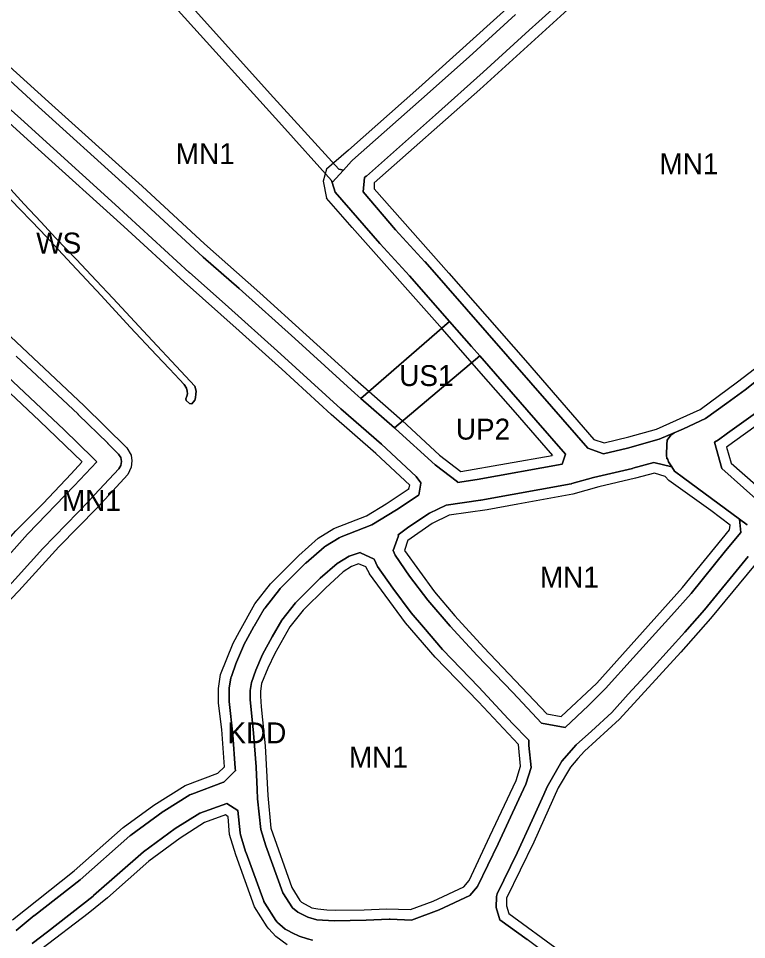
# Model space of a CAD drawing. Extents: x -284239 to -281592, y 34477 to 37267.
# Drawn here: x -283861.3 to -283512.6, y 35288.9 to 35729.6 of the extents above; entities that cross this region are included whole.
import ezdxf

# ---------------------------------------------------------------- set-up
doc = ezdxf.new("R2010")
doc.units = 0
for name, color, linetype in [('linie_rozgraniczajace', 7, 'Continuous'), ('linie_zabudowy_nieprzekraczalne', 7, 'Continuous'), ('oznaczenia_przeznaczen', 7, 'Continuous')]:
    doc.layers.add(name, color=color, linetype=linetype)

msp = doc.modelspace()

# ---------------------------------------------------------------- linework, layer by layer
at = {"layer": 'linie_rozgraniczajace'}
for points in [[(-283808.955, 35769.886), (-283783.5, 35741.024), (-283780.8, 35738.036), (-283740.666, 35693.613), (-283707.899, 35657.552), (-283705.683, 35657.06), (-283711.093, 35651.189), (-283711.377, 35652.06), (-283735.174, 35678.603), (-283784.744, 35733.443), (-283790.273, 35739.559), (-283815.534, 35767.383), (-283817.232, 35767.227), (-283817.23, 35767.269), (-283824.445, 35774.068), (-283832.86, 35774.502)], [(-283582.255, 35755.055), (-283612.122, 35728.101), (-283616.645, 35723.99), (-283638.785, 35703.867), (-283638.811, 35703.846), (-283661.609, 35683.477), (-283694.657, 35654.221), (-283694.732, 35654.154), (-283695.579, 35653.436), (-283696.185, 35646.675), (-283680.653, 35628.497), (-283666.588, 35613.191), (-283666.552, 35613.135), (-283666.511, 35613.105), (-283636.802, 35579.241), (-283605.981, 35543.988), (-283588.549, 35523.959), (-283581.071, 35521.348), (-283569.642, 35524.059), (-283554.422, 35528.287), (-283547.243, 35531.389), (-283548.812, 35530.257), (-283550.583, 35527.86), (-283550.792, 35525.775), (-283550.896, 35520.877), (-283550.711, 35518.939), (-283550.518, 35518.992), (-283550.062, 35517.542), (-283548.466, 35515.033), (-283556.983, 35517.221), (-283567.06, 35514.398), (-283567.127, 35514.388), (-283567.249, 35514.349), (-283585.931, 35509.938), (-283596.199, 35507.032), (-283596.388, 35507.006), (-283596.669, 35506.923), (-283639.858, 35499.094), (-283639.977, 35499.083), (-283640.053, 35499.063), (-283656.447, 35496.757), (-283664.447, 35492.93), (-283674.315, 35486.435), (-283679.45, 35482.48), (-283679.321, 35482.071), (-283681.841, 35475.084), (-283680.864, 35472.739), (-283673.957, 35462.829), (-283665.249, 35451.269), (-283654.589, 35438.807), (-283641.677, 35424.844), (-283624.486, 35407.053)], [(-283496.755, 35565.013), (-283513.325, 35551.986), (-283522.028, 35545.577), (-283532.345, 35538.177), (-283542.871, 35533.279), (-283547.243, 35531.389), (-283554.422, 35528.287), (-283569.642, 35524.059), (-283581.071, 35521.348), (-283588.549, 35523.959), (-283605.981, 35543.988), (-283636.802, 35579.241), (-283666.511, 35613.105), (-283666.552, 35613.135), (-283666.588, 35613.191), (-283680.653, 35628.497), (-283696.185, 35646.675), (-283695.579, 35653.436), (-283694.732, 35654.154), (-283694.657, 35654.221), (-283661.609, 35683.477), (-283638.811, 35703.846), (-283638.785, 35703.867), (-283616.645, 35723.99), (-283612.122, 35728.101), (-283582.255, 35755.055)], [(-283623.204, 35731.542), (-283645.495, 35711.281), (-283668.253, 35690.949), (-283701.237, 35661.749), (-283701.793, 35661.281), (-283705.683, 35657.06), (-283707.899, 35657.552), (-283740.666, 35693.613), (-283780.8, 35738.036)], [(-283784.744, 35733.443), (-283735.174, 35678.603), (-283711.377, 35652.06), (-283711.093, 35651.189), (-283709.551, 35646.459), (-283688.197, 35621.932), (-283688.134, 35621.887), (-283688.077, 35621.797), (-283673.99, 35606.467), (-283654.775, 35584.565), (-283697.303, 35547.75), (-283700.247, 35550.318), (-283728.872, 35576.454), (-283728.901, 35576.477), (-283755.566, 35600.375), (-283755.59, 35600.39), (-283755.606, 35600.413), (-283772.734, 35615.466), (-283808.228, 35648.053), (-283853.453, 35688.985), (-283875.706, 35709.29)], [(-283875.706, 35709.29), (-283853.453, 35688.985), (-283808.228, 35648.053), (-283772.734, 35615.466), (-283755.606, 35600.413), (-283755.59, 35600.39), (-283755.566, 35600.375), (-283728.901, 35576.477), (-283728.872, 35576.454), (-283700.247, 35550.318), (-283697.303, 35547.75), (-283681.245, 35533.742), (-283680.762, 35533.321), (-283680.718, 35533.26), (-283680.635, 35533.206), (-283661.767, 35516.043), (-283651.032, 35507.834), (-283650.975, 35507.625), (-283641.544, 35508.951), (-283600.922, 35516.315), (-283600.896, 35516.422), (-283599.331, 35521.115), (-283613.517, 35537.415), (-283640.395, 35568.158), (-283644.325, 35572.653), (-283654.775, 35584.565), (-283673.99, 35606.467), (-283688.077, 35621.797), (-283688.134, 35621.887), (-283688.197, 35621.932), (-283709.551, 35646.459), (-283711.093, 35651.189), (-283705.683, 35657.06), (-283701.793, 35661.281), (-283701.237, 35661.749), (-283668.253, 35690.949), (-283645.495, 35711.281), (-283623.204, 35731.542)], [(-283714.87, 35476.613), (-283714.661, 35476.741), (-283714.236, 35477.078), (-283707.712, 35481.123), (-283706.991, 35481.493), (-283706.797, 35481.532), (-283706.659, 35481.617), (-283692.076, 35487.249), (-283680.271, 35494.47), (-283680.14, 35494.546), (-283679.969, 35494.686), (-283669.661, 35501.471), (-283669.616, 35501.494), (-283668.586, 35507.329), (-283668.529, 35507.443), (-283670.842, 35510.369), (-283687.4, 35525.841), (-283706.863, 35542.82), (-283706.892, 35542.859), (-283706.948, 35542.895), (-283735.598, 35569.054), (-283762.222, 35592.912), (-283779.377, 35607.992), (-283779.404, 35608.03), (-283779.457, 35608.064), (-283814.967, 35640.666), (-283860.177, 35681.585), (-283882.985, 35701.865)], [(-283882.985, 35701.865), (-283860.177, 35681.585), (-283814.967, 35640.666), (-283779.457, 35608.064), (-283779.404, 35608.03), (-283779.377, 35607.992), (-283762.222, 35592.912), (-283735.598, 35569.054), (-283706.948, 35542.895), (-283706.892, 35542.859), (-283706.863, 35542.82), (-283687.4, 35525.841), (-283670.842, 35510.369), (-283668.529, 35507.443), (-283668.586, 35507.329), (-283669.616, 35501.494), (-283669.661, 35501.471), (-283679.969, 35494.686), (-283680.14, 35494.546), (-283680.271, 35494.47), (-283692.076, 35487.249), (-283706.659, 35481.617), (-283706.797, 35481.532), (-283706.991, 35481.493), (-283707.712, 35481.123), (-283714.236, 35477.078), (-283714.661, 35476.741), (-283714.87, 35476.613)], [(-283864.887, 35642.802), (-283850.707, 35628.208), (-283835.698, 35612.105), (-283821.67, 35596.983), (-283807.792, 35581.937), (-283795.197, 35568.474), (-283788.937, 35561.95), (-283784.185, 35556.821), (-283781.922, 35554.407), (-283780.791, 35552.748), (-283780.414, 35551.315), (-283780.339, 35550.033), (-283780.565, 35548.826), (-283781.093, 35547.62), (-283780.942, 35546.79), (-283779.358, 35545.432), (-283778.302, 35545.206), (-283776.718, 35546.941), (-283776.492, 35548.148), (-283776.341, 35550.033), (-283776.19, 35551.164), (-283776.417, 35552.597), (-283776.794, 35553.729), (-283783.431, 35560.856), (-283799.269, 35577.788), (-283816.013, 35595.776), (-283823.932, 35604.073), (-283833.662, 35614.368), (-283843.391, 35624.512), (-283850.556, 35632.281), (-283858.476, 35640.766), (-283871.373, 35654.832)], [(-283871.373, 35654.832), (-283858.476, 35640.766), (-283850.556, 35632.281), (-283843.391, 35624.512), (-283833.662, 35614.368), (-283823.932, 35604.073), (-283816.013, 35595.776), (-283799.269, 35577.788), (-283783.431, 35560.856), (-283776.794, 35553.729), (-283776.417, 35552.597), (-283776.19, 35551.164), (-283776.341, 35550.033), (-283776.492, 35548.148), (-283776.718, 35546.941), (-283778.302, 35545.206), (-283779.358, 35545.432), (-283780.942, 35546.79), (-283781.093, 35547.62), (-283780.565, 35548.826), (-283780.339, 35550.033), (-283780.414, 35551.315), (-283780.791, 35552.748), (-283781.922, 35554.407), (-283784.185, 35556.821), (-283788.937, 35561.95), (-283795.197, 35568.474), (-283807.792, 35581.937), (-283821.67, 35596.983), (-283835.698, 35612.105), (-283850.707, 35628.208), (-283864.887, 35642.802)], [(-283862.396, 35568.049), (-283832.706, 35540.21), (-283832.681, 35540.175), (-283832.641, 35540.148), (-283818.486, 35526.39), (-283818.447, 35526.333), (-283818.39, 35526.294), (-283813.297, 35521.069), (-283812.258, 35519.492), (-283811.877, 35517.579), (-283812.258, 35515.665), (-283813.216, 35514.174), (-283827.239, 35499.093), (-283827.281, 35499.063), (-283827.313, 35499.014), (-283849.606, 35476.062), (-283868.791, 35454.767)], [(-283868.791, 35454.767), (-283849.606, 35476.062), (-283827.313, 35499.014), (-283827.281, 35499.063), (-283827.239, 35499.093), (-283813.216, 35514.174), (-283812.258, 35515.665), (-283811.877, 35517.579), (-283812.258, 35519.492), (-283813.297, 35521.069), (-283818.39, 35526.294), (-283818.447, 35526.333), (-283818.486, 35526.39), (-283832.641, 35540.148), (-283832.681, 35540.175), (-283832.706, 35540.21), (-283862.396, 35568.049)], [(-283512.308, 35487.34), (-283516.02, 35490.071), (-283542.871, 35509.83), (-283547.144, 35512.956), (-283548.466, 35515.033), (-283550.062, 35517.542), (-283550.518, 35518.992), (-283550.711, 35518.939), (-283550.896, 35520.877), (-283550.792, 35525.775), (-283550.583, 35527.86), (-283548.812, 35530.257), (-283547.243, 35531.389), (-283542.871, 35533.279), (-283532.345, 35538.177), (-283522.028, 35545.577), (-283513.325, 35551.986), (-283496.755, 35565.013)], [(-283876.156, 35461.533), (-283856.972, 35482.826), (-283856.901, 35482.875), (-283856.844, 35482.962), (-283834.525, 35505.942), (-283823.78, 35517.497), (-283825.504, 35519.266), (-283839.578, 35532.946), (-283869.253, 35560.771)], [(-283869.253, 35560.771), (-283839.578, 35532.946), (-283825.504, 35519.266), (-283823.78, 35517.497), (-283834.525, 35505.942), (-283856.844, 35482.962), (-283856.901, 35482.875), (-283856.972, 35482.826), (-283876.156, 35461.533)], [(-283507.177, 35541.564), (-283521.715, 35531.195), (-283525.988, 35527.964), (-283527.946, 35526.924), (-283524.385, 35514.239), (-283503.633, 35495.708)], [(-283503.633, 35495.708), (-283524.385, 35514.239), (-283527.946, 35526.924), (-283525.988, 35527.964), (-283521.715, 35531.195), (-283507.177, 35541.564)], [(-283624.486, 35407.053), (-283615.328, 35397.143), (-283610.767, 35392.355), (-283599.518, 35390.409), (-283588.303, 35400.897), (-283580.12, 35408.93), (-283566.908, 35423.643), (-283548.516, 35443.987), (-283539.057, 35454.497), (-283522.617, 35474.841), (-283515.386, 35483.607), (-283516.02, 35490.071), (-283512.308, 35487.34)], [(-283862.327, 35293.261), (-283853.715, 35300.32), (-283853.69, 35300.335), (-283853.628, 35300.389), (-283831.779, 35317.5), (-283807.875, 35338.507), (-283807.792, 35338.559), (-283807.519, 35338.792), (-283791.909, 35350.169), (-283791.743, 35350.262), (-283791.589, 35350.383), (-283779.154, 35358.057), (-283778.442, 35358.421), (-283778.344, 35358.44), (-283778.268, 35358.489), (-283763.121, 35364.111), (-283762.9, 35364.151), (-283757.468, 35369.583), (-283757.377, 35369.666), (-283757.434, 35370.885), (-283758.597, 35386.779), (-283760.348, 35402.804), (-283760.378, 35403.347), (-283760.378, 35408.436), (-283760.31, 35409.258), (-283759.527, 35413.956), (-283759.334, 35414.63), (-283759.3, 35414.827), (-283756.951, 35421.351), (-283756.868, 35421.482), (-283756.834, 35421.646), (-283753.435, 35429.484), (-283753.258, 35429.853), (-283748.561, 35438.596), (-283748.527, 35438.642), (-283748.462, 35438.771), (-283743.569, 35447.057), (-283743.341, 35447.351), (-283743.185, 35447.617), (-283736.269, 35456.359), (-283735.883, 35456.792), (-283723.749, 35468.927), (-283723.579, 35469.041), (-283723.481, 35469.176), (-283714.87, 35476.613)], [(-283714.87, 35476.613), (-283723.481, 35469.176), (-283723.579, 35469.041), (-283723.749, 35468.927), (-283735.883, 35456.792), (-283736.269, 35456.359), (-283743.185, 35447.617), (-283743.341, 35447.351), (-283743.569, 35447.057), (-283748.462, 35438.771), (-283748.527, 35438.642), (-283748.561, 35438.596), (-283753.258, 35429.853), (-283753.435, 35429.484), (-283756.834, 35421.646), (-283756.868, 35421.482), (-283756.951, 35421.351), (-283759.3, 35414.827), (-283759.334, 35414.63), (-283759.527, 35413.956), (-283760.31, 35409.258), (-283760.378, 35408.436), (-283760.378, 35403.347), (-283760.348, 35402.804), (-283758.597, 35386.779), (-283757.434, 35370.885), (-283757.377, 35369.666), (-283757.468, 35369.583), (-283762.9, 35364.151), (-283763.121, 35364.111), (-283778.268, 35358.489), (-283778.344, 35358.44), (-283778.442, 35358.421), (-283779.154, 35358.057), (-283791.589, 35350.383), (-283791.743, 35350.262), (-283791.909, 35350.169), (-283807.519, 35338.792), (-283807.792, 35338.559), (-283807.875, 35338.507), (-283831.779, 35317.5), (-283853.628, 35300.389), (-283853.69, 35300.335), (-283853.715, 35300.32), (-283862.327, 35293.261)], [(-283511.807, 35472.138), (-283532.826, 35446.614), (-283542.135, 35435.955), (-283557.224, 35419.364), (-283569.31, 35406.227), (-283577.117, 35397.519), (-283586.876, 35388.661), (-283594.158, 35381.979), (-283601.125, 35374.211), (-283608.121, 35362.011), (-283609.622, 35358.258), (-283615.253, 35346.021), (-283622.459, 35330.407), (-283631.993, 35310.813), (-283632.294, 35309.462), (-283632.444, 35304.207), (-283630.702, 35298.362), (-283617.703, 35288.854)], [(-283632.444, 35304.207), (-283632.294, 35309.462), (-283631.993, 35310.813), (-283622.459, 35330.407), (-283615.253, 35346.021), (-283609.622, 35358.258), (-283608.121, 35362.011), (-283601.125, 35374.211), (-283594.158, 35381.979), (-283586.876, 35388.661), (-283577.117, 35397.519), (-283569.31, 35406.227), (-283557.224, 35419.364), (-283542.135, 35435.955), (-283532.826, 35446.614), (-283511.807, 35472.138)], [(-283720.495, 35288.596), (-283722.896, 35289.305), (-283726.771, 35290.451), (-283730.258, 35292.156), (-283732.339, 35293.174), (-283733.503, 35293.917), (-283736.076, 35296.108), (-283737.026, 35296.917), (-283737.319, 35297.188), (-283737.974, 35297.997), (-283743.324, 35306.217), (-283743.753, 35307.031), (-283743.832, 35307.237), (-283752.248, 35330.397), (-283752.321, 35330.613), (-283754.931, 35338.964), (-283755.133, 35339.95), (-283756.213, 35350.651), (-283761.515, 35354.041), (-283774.324, 35349.286), (-283786.174, 35341.974), (-283801.445, 35330.845), (-283825.284, 35309.895), (-283825.331, 35309.866), (-283825.502, 35309.714), (-283847.419, 35292.551), (-283854.627, 35287.038)], [(-283854.627, 35287.038), (-283847.419, 35292.551), (-283825.502, 35309.714), (-283825.331, 35309.866), (-283825.284, 35309.895), (-283801.445, 35330.845), (-283786.174, 35341.974), (-283774.324, 35349.286), (-283761.515, 35354.041), (-283756.213, 35350.651), (-283755.133, 35339.95), (-283754.931, 35338.964), (-283752.321, 35330.613), (-283752.248, 35330.397), (-283743.832, 35307.237), (-283743.753, 35307.031), (-283743.324, 35306.217), (-283737.974, 35297.997), (-283737.319, 35297.188), (-283737.026, 35296.917), (-283736.076, 35296.108), (-283733.503, 35293.917), (-283732.339, 35293.174), (-283730.258, 35292.156), (-283726.771, 35290.451), (-283722.896, 35289.305), (-283720.495, 35288.596)], [(-283460.618, 35234.062), (-283475.613, 35245.965), (-283496.173, 35262.042), (-283502.975, 35267.607), (-283509.313, 35257.095), (-283522.917, 35232.825), (-283522.917, 35232.636), (-283523.014, 35232.725), (-283527.552, 35226.283), (-283534.386, 35231.101), (-283550.521, 35241.633), (-283553.587, 35243.683), (-283559.988, 35247.963), (-283568.279, 35253.341), (-283582.285, 35262.753), (-283579.201, 35266.417), (-283588.366, 35276.203), (-283598.698, 35279.683), (-283601.902, 35277.142), (-283617.703, 35288.854), (-283630.702, 35298.362), (-283632.444, 35304.207)]]:
    msp.add_lwpolyline(points, dxfattribs=at)
for points in [[(-283697.303, 35547.75), (-283654.775, 35584.565), (-283644.325, 35572.653), (-283640.395, 35568.158), (-283681.245, 35533.742)], [(-283681.245, 35533.742), (-283640.395, 35568.158), (-283613.517, 35537.415), (-283599.331, 35521.115), (-283600.896, 35516.422), (-283600.922, 35516.315), (-283641.544, 35508.951), (-283650.975, 35507.625), (-283651.032, 35507.834), (-283661.767, 35516.043), (-283680.635, 35533.206), (-283680.718, 35533.26), (-283680.762, 35533.321)], [(-283681.841, 35475.084), (-283679.321, 35482.071), (-283679.45, 35482.48), (-283674.315, 35486.435), (-283664.447, 35492.93), (-283656.447, 35496.757), (-283640.053, 35499.063), (-283639.977, 35499.083), (-283639.858, 35499.094), (-283596.669, 35506.923), (-283596.388, 35507.006), (-283596.199, 35507.032), (-283585.931, 35509.938), (-283567.249, 35514.349), (-283567.127, 35514.388), (-283567.06, 35514.398), (-283556.983, 35517.221), (-283548.466, 35515.033), (-283547.144, 35512.956), (-283542.871, 35509.83), (-283516.02, 35490.071), (-283515.386, 35483.607), (-283522.617, 35474.841), (-283539.057, 35454.497), (-283548.516, 35443.987), (-283566.908, 35423.643), (-283580.12, 35408.93), (-283588.303, 35400.897), (-283599.518, 35390.409), (-283610.767, 35392.355), (-283615.328, 35397.143), (-283624.486, 35407.053), (-283641.677, 35424.844), (-283654.589, 35438.807), (-283665.249, 35451.269), (-283673.957, 35462.829), (-283680.864, 35472.739)], [(-283750.378, 35403.62), (-283748.646, 35387.776), (-283748.638, 35387.634), (-283748.63, 35387.598), (-283747.456, 35371.549), (-283747.464, 35371.493), (-283747.448, 35371.417), (-283746.946, 35360.712), (-283746.736, 35356.222), (-283745.236, 35341.464), (-283742.811, 35333.705), (-283734.63, 35311.191), (-283729.989, 35304.059), (-283727.498, 35301.938), (-283725.866, 35301.14), (-283722.612, 35299.549), (-283718.348, 35298.377), (-283710.008, 35297.878), (-283694.742, 35298.136), (-283683.761, 35298.659), (-283683.523, 35298.618), (-283683.286, 35298.659), (-283672.988, 35298.169), (-283659.844, 35303.081), (-283645.13, 35309.988), (-283641.377, 35314.192), (-283631.618, 35334.761), (-283621.634, 35356.005), (-283618.331, 35363.212), (-283615.726, 35371.164), (-283616.871, 35381.664), (-283616.871, 35384.343), (-283617.13, 35384.682), (-283624.636, 35392.339), (-283640.776, 35409.68), (-283658.268, 35427.622), (-283667.276, 35438.282), (-283673.281, 35445.188), (-283682.065, 35456.974), (-283689.271, 35467.333), (-283690.969, 35470.971), (-283697.506, 35473.989), (-283697.642, 35474.082), (-283702.94, 35472.316), (-283708.632, 35468.787), (-283716.807, 35461.727), (-283728.607, 35449.927), (-283735.131, 35441.679), (-283739.8, 35433.773), (-283744.35, 35425.305), (-283747.596, 35417.815), (-283749.737, 35411.865), (-283750.378, 35408.023)], [(-283750.378, 35403.62), (-283750.378, 35408.023), (-283749.737, 35411.865), (-283747.596, 35417.815), (-283744.35, 35425.305), (-283739.8, 35433.773), (-283735.131, 35441.679), (-283728.607, 35449.927), (-283716.807, 35461.727), (-283708.632, 35468.787), (-283702.94, 35472.316), (-283697.642, 35474.082), (-283697.506, 35473.989), (-283690.969, 35470.971), (-283689.271, 35467.333), (-283682.065, 35456.974), (-283673.281, 35445.188), (-283667.276, 35438.282), (-283658.268, 35427.622), (-283640.776, 35409.68), (-283624.636, 35392.339), (-283617.13, 35384.682), (-283616.871, 35384.343), (-283616.871, 35381.664), (-283615.726, 35371.164), (-283618.331, 35363.212), (-283621.634, 35356.005), (-283631.618, 35334.761), (-283641.377, 35314.192), (-283645.13, 35309.988), (-283659.844, 35303.081), (-283672.988, 35298.169), (-283683.286, 35298.659), (-283683.523, 35298.618), (-283683.761, 35298.659), (-283694.742, 35298.136), (-283710.008, 35297.878), (-283718.348, 35298.377), (-283722.612, 35299.549), (-283725.866, 35301.14), (-283727.498, 35301.938), (-283729.989, 35304.059), (-283734.63, 35311.191), (-283742.811, 35333.705), (-283745.236, 35341.464), (-283746.736, 35356.222), (-283746.946, 35360.712), (-283747.448, 35371.417), (-283747.464, 35371.493), (-283747.456, 35371.549), (-283748.63, 35387.598), (-283748.638, 35387.634), (-283748.646, 35387.776)]]:
    msp.add_lwpolyline(points, close=True, dxfattribs=at)
at = {"layer": 'linie_zabudowy_nieprzekraczalne'}
for points in [[(-283703.254, 35666.597), (-283669.574, 35696.441), (-283633.723, 35728.654), (-283600.253, 35759.015), (-283562.286, 35793.411), (-283529.742, 35822.383)], [(-283591.125, 35740.362), (-283640.338, 35695.581), (-283690.873, 35650.932), (-283690.873, 35648.154), (-283655.154, 35607.739), (-283618.51, 35566.001), (-283585.701, 35528.166), (-283580.806, 35526.578), (-283569.032, 35529.489), (-283555.803, 35533.127), (-283534.901, 35542.519), (-283516.909, 35555.748), (-283503.416, 35566.133), (-283481.323, 35583.993), (-283454.6, 35607.21), (-283426.422, 35633.139), (-283399.831, 35656.819), (-283394.804, 35661.847)], [(-283882.491, 35724.719), (-283872.569, 35712.813), (-283846.845, 35689.694), (-283801.999, 35649.411), (-283772.233, 35621.762), (-283745.642, 35598.28), (-283701.324, 35558.064), (-283677.512, 35537.294), (-283659.652, 35520.691), (-283649.466, 35512.886), (-283605.677, 35520.427)], [(-283674.337, 35504.75), (-283673.808, 35506.337), (-283690.08, 35521.419), (-283711.511, 35540.138), (-283735.059, 35561.834), (-283755.564, 35580.156), (-283781.89, 35603.572), (-283810.862, 35630.097), (-283851.74, 35667.138), (-283902.41, 35712.781)], [(-283703.254, 35666.597), (-283713.758, 35657.454), (-283715.283, 35651.769), (-283713.783, 35643.676)], [(-283605.413, 35520.427), (-283624.33, 35542.321), (-283638.618, 35558.46), (-283658.197, 35581.016), (-283701.457, 35629.633), (-283713.783, 35643.676)], [(-283830.706, 35517.45), (-283851.211, 35537.095), (-283885.078, 35568.845), (-283906.641, 35588.954), (-283918.68, 35576.717), (-283937.598, 35557.402), (-283966.967, 35526.247), (-284004.67, 35487.287), (-284027.027, 35464.401), (-284026.895, 35461.623), (-284004.802, 35440.654), (-283975.566, 35412.609), (-283952.944, 35389.987), (-283951.224, 35389.987), (-283927.014, 35414.527), (-283903.996, 35440.258), (-283879.786, 35464.996), (-283862.456, 35484.443), (-283849.491, 35497.606), (-283835.998, 35511.761), (-283830.97, 35517.318)], [(-283873.172, 35584.985), (-283829.912, 35544.437), (-283809.407, 35524.197), (-283807.29, 35520.625), (-283806.893, 35517.979), (-283807.29, 35514.936), (-283808.878, 35511.365), (-283823.562, 35495.489), (-283841.951, 35476.836), (-283861.001, 35455.67), (-283889.179, 35426.565)], [(-283399.708, 35511.798), (-283404.726, 35516.59), (-283423.379, 35534.317), (-283438.989, 35550.391), (-283457.907, 35571.557), (-283461.876, 35571.822), (-283483.175, 35553.896), (-283504.077, 35537.492), (-283522.201, 35524.528), (-283519.952, 35516.855), (-283501.696, 35500.715), (-283467.565, 35470.023), (-283453.022, 35455.97)], [(-283674.734, 35479.945), (-283676.453, 35475.05), (-283662.034, 35455.207), (-283652.376, 35443.829), (-283638.353, 35428.55), (-283608.191, 35396.932), (-283601.312, 35395.609), (-283584.378, 35411.55), (-283543.236, 35457.389), (-283520.746, 35484.906), (-283520.481, 35487.155), (-283529.742, 35494.1), (-283549.85, 35508.52), (-283551.57, 35510.505), (-283556.729, 35512.092), (-283565.857, 35509.579), (-283583.32, 35505.478), (-283595.755, 35501.972), (-283622.081, 35497.209), (-283636.766, 35494.431), (-283655.022, 35491.918), (-283663.224, 35487.949), (-283674.866, 35479.879)], [(-283864.043, 35298.308), (-283834.542, 35321.724), (-283811.127, 35342.428), (-283796.442, 35353.143), (-283781.361, 35362.668), (-283765.751, 35368.423), (-283762.576, 35371.466), (-283763.898, 35389.457), (-283765.486, 35402.025), (-283765.486, 35409.037), (-283764.428, 35415.717), (-283758.474, 35430.666), (-283755.432, 35436.355), (-283748.023, 35449.584), (-283740.615, 35459.109), (-283726.989, 35472.669), (-283717.729, 35480.871), (-283710.188, 35485.634), (-283694.577, 35491.587), (-283685.185, 35497.408), (-283674.205, 35504.684)], [(-283505.4, 35472.008), (-283529.874, 35442.44), (-283544.029, 35426.433), (-283573.398, 35394.352), (-283590.199, 35379.006), (-283593.374, 35375.435), (-283596.946, 35371.4), (-283602.767, 35361.478), (-283614.541, 35335.482), (-283627.505, 35308.759), (-283627.505, 35305.055), (-283626.447, 35301.351), (-283601.973, 35283.492), (-283600.65, 35284.418), (-283598.004, 35284.748), (-283585.172, 35280.118), (-283576.839, 35271.442), (-283574.995, 35268.777), (-283576.583, 35264.015), (-283578.302, 35260.046)], [(-283692.99, 35463.739), (-283694.842, 35467.179), (-283698.414, 35468.634), (-283701.721, 35467.311), (-283705.69, 35464.864), (-283714.289, 35457.059), (-283724.872, 35446.475), (-283731.355, 35438.472), (-283738.498, 35425.772), (-283741.806, 35418.76), (-283744.848, 35411.352), (-283745.378, 35407.78), (-283745.378, 35405.266), (-283744.981, 35400.173), (-283743.129, 35381.652), (-283741.806, 35357.84), (-283740.483, 35342.163), (-283730.429, 35313.853), (-283726.592, 35307.503), (-283725.798, 35306.709), (-283720.771, 35304.063), (-283717.861, 35303.534), (-283713.628, 35303.137), (-283709.526, 35303.005), (-283695.636, 35303.071), (-283685.052, 35303.6), (-283673.543, 35303.203), (-283662.695, 35307.304), (-283648.011, 35314.051), (-283645.497, 35317.094), (-283635.575, 35338.327), (-283623.008, 35365.05), (-283620.891, 35371.797), (-283621.817, 35382.181), (-283640.999, 35402.554), (-283661.769, 35423.986), (-283675.924, 35440.39), (-283693.122, 35463.806)], [(-283732.555, 35286.372), (-283737.979, 35290.341), (-283741.327, 35294.009), (-283742.203, 35295.001), (-283748.156, 35304.526), (-283757.152, 35329.463), (-283760.194, 35339.12), (-283760.856, 35347.587), (-283762.046, 35348.513), (-283772.101, 35344.941), (-283783.875, 35337.401), (-283798.824, 35326.42), (-283818.667, 35308.892), (-283827.928, 35301.351), (-283850.02, 35284.418)]]:
    msp.add_lwpolyline(points, dxfattribs=at)

# ---------------------------------------------------------------- texts
at = {"layer": 'oznaczenia_przeznaczen'}
for s, p in [('MN1', (-283785.946, 35659.898)), ('MN1', (-283554.286, 35655.066)), ('WS', (-283852.746, 35617.141)), ('US1', (-283678.926, 35553.723)), ('UP2', (-283651.802, 35528.108)), ('MN1', (-283840.442, 35494.014)), ('MN1', (-283611.559, 35457.257)), ('KDD', (-283761.219, 35382.776)), ('MN1', (-283703.019, 35371.129))]:
    msp.add_text(s, height=10, dxfattribs=at).set_placement(p)

doc.saveas('drawing.dxf')
